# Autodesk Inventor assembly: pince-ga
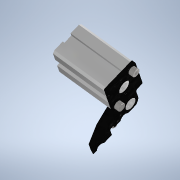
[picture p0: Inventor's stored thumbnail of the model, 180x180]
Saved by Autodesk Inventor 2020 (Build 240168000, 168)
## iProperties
Created: 2023-10
Part Number: pince-ga
Document SubType Name: Assembly
Designer: bruno
Mass: 100.514 g
Surface Area: 169.178 cm^2
Volume: 39.5172 cm^3
Density: 2.54356 g/cm^3
Author: bruno
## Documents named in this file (6)
- C:\Users\bruno\Documents\1-Cours-2023-24\Maquettes-Inventor\Pince-robot-Dobot\pince-ga.iam
- C:\Users\bruno\Documents\1-Cours-2023-24\Maquettes-Inventor\Pince-robot-Dobot\pince-g.ipt
- C:\Users\bruno\Documents\1-Cours-2023-24\Maquettes-Inventor\Pince-robot-Dobot\Douille.ipt
- C:\Users\bruno\Documents\1-Cours-2023-24\Maquettes-Inventor\Pince-robot-Dobot\corps-verin.ipt
- C:\Users\bruno\Documents\Inventor\Content Center Files\R2020\fr-FR\KS B 1003\KS B 1003 - M 4 x 8.ipt
- C:\Users\bruno\Documents\Inventor\Content Center Files\R2020\fr-FR\KS B 1003\KS B 1003 - M 3 x 10.ipt
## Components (6 placed, 5 different names)
1. pince-g:1 — Placage:1, Affleurement:1, Placage:2, Placage:3, Angle:1, Logement:1, Logement:2, Logement:3
2. Douille:1 — Placage:1, Affleurement:1
3. corps-verin:1 — Placage:2, Placage:3, Angle:1
4. KS B 1003 - Métrique M 4 x 8:1 — Logement:1
5. KS B 1003 - Métrique M 4 x 8:2 — Logement:2
6. KS B 1003 - Métrique M 3 x 10:1 — Logement:3
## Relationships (8: Mate 3, Insert 3, Flush 1, Angle 1)
- Placage:1 [Mate]: pince-g:1 ↔ Douille:1
- Affleurement:1 [Flush]: pince-g:1 ↔ Douille:1
- Placage:2 [Mate]: pince-g:1 ↔ corps-verin:1
- Placage:3 [Mate]: pince-g:1 ↔ corps-verin:1
- Angle:1: pince-g:1 ↔ corps-verin:1
- Logement:1 [Insert]: pince-g:1 ↔ KS B 1003 - Métrique M 4 x 8:1
- Logement:2 [Insert]: pince-g:1 ↔ KS B 1003 - Métrique M 4 x 8:2
- Logement:3 [Insert]: pince-g:1 ↔ KS B 1003 - Métrique M 3 x 10:1
